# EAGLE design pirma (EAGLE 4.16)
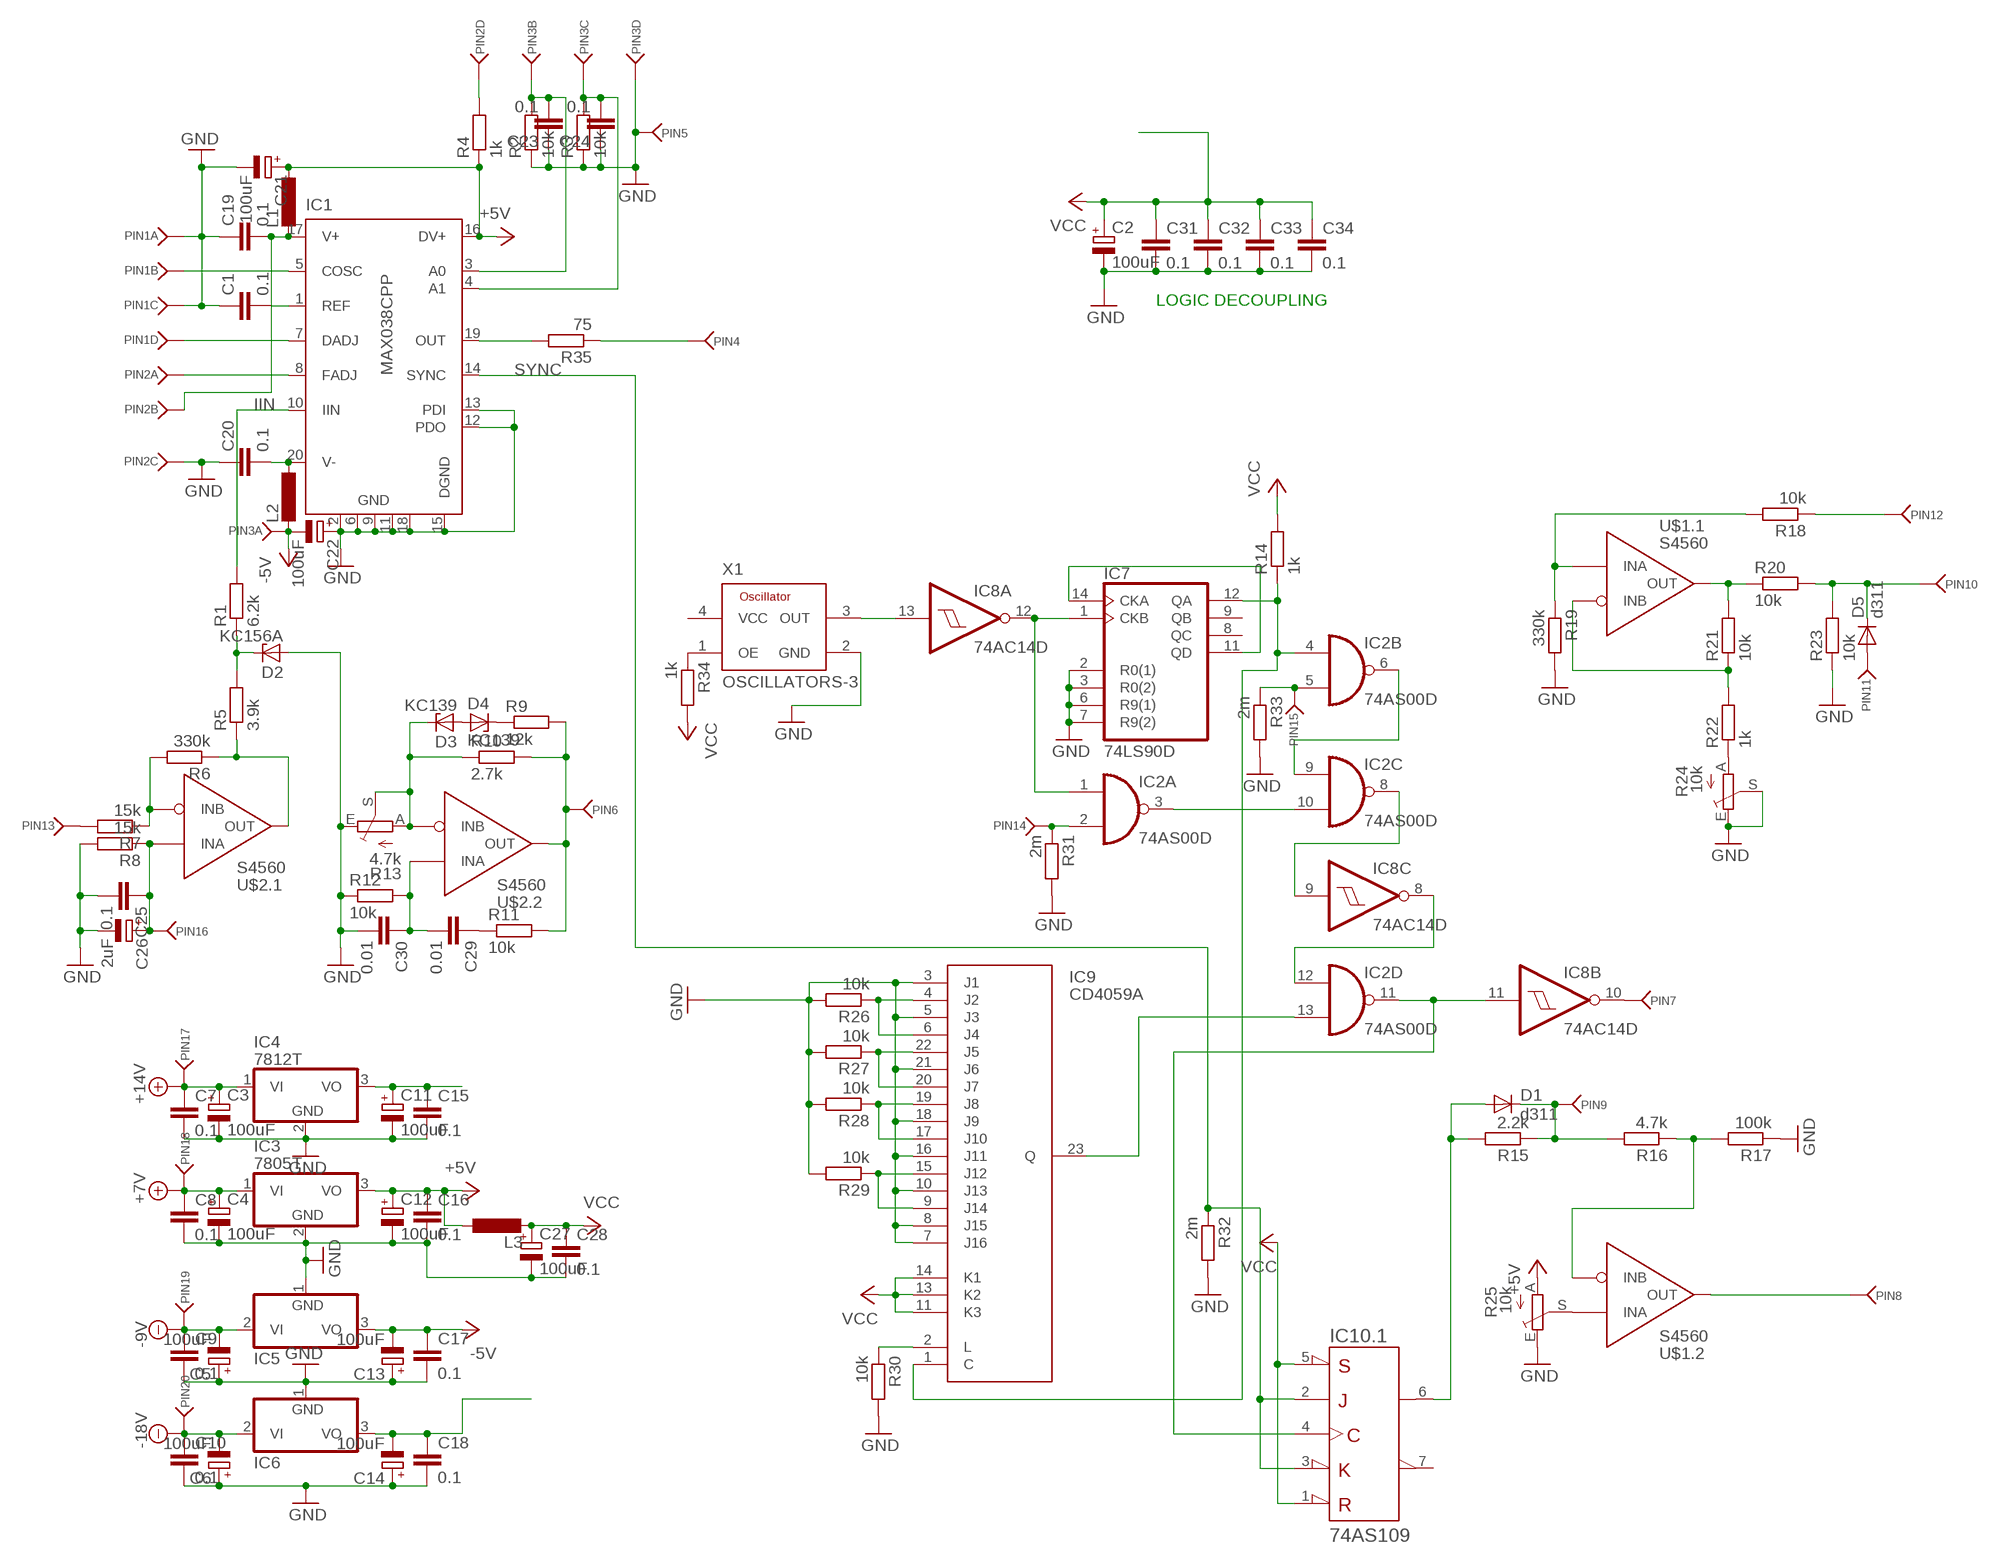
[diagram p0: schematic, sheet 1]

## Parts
C1  0.1  C-EUC1206K  [C1206K]
C2  100uF  CPOL-EUSMCD  [SMC_D]
C3  100uF  CPOL-EUSMCB  [SMC_B]
C4  100uF  CPOL-EUSMCB  [SMC_B]
C5  100uF  CPOL-EUSMCB  [SMC_B]
C6  100uF  CPOL-EUSMCD  [SMC_D]
C7  0.1  C-EUC1206K  [C1206K]
C8  0.1  C-EUC1206K  [C1206K]
C9  0.1  C-EUC1206K  [C1206K]
C10  0.1  C-EUC1206K  [C1206K]
C11  100uF  CPOL-EUSMCB  [SMC_B]
C12  100uF  CPOL-EUSMCD  [SMC_D]
C13  100uF  CPOL-EUSMCB  [SMC_B]
C14  100uF  CPOL-EUSMCB  [SMC_B]
C15  0.1  C-EUC1206K  [C1206K]
C16  0.1  C-EUC1206K  [C1206K]
C17  0.1  C-EUC1206K  [C1206K]
C18  0.1  C-EUC1206K  [C1206K]
C19  0.1  C-EUC1206K  [C1206K]
C20  0.1  C-EUC1206K  [C1206K]
C21  100uF  CPOL-EUSMCD  [SMC_D]
C22  100uF  CPOL-EUSMCB  [SMC_B]
C23  0.1  C-EUC1206K  [C1206K]
C24  0.1  C-EUC1206K  [C1206K]
C25  0.1  C-EUC1206K  [C1206K]
C26  2uF  CPOL-EUSMCB  [SMC_B]
C27  100uF  CPOL-EUSMCB  [SMC_B]
C28  0.1  C-EUC1206K  [C1206K]
C29  0.01  C-EUC1206K  [C1206K]
C30  0.01  C-EUC1206K  [C1206K]
C31  0.1  C-EUC1206K  [C1206K]
C32  0.1  C-EUC1206K  [C1206K]
C33  0.1  C-EUC1206K  [C1206K]
C34  0.1  C-EUC1206K  [C1206K]
D1  d311  DIODE-DO214AA  [DO214AA]
D2  KC156A  ZENER-DIODESMB  [SMB]
D3  KC139  ZENER-DIODESMB  [SMB]
D4  KC139  ZENER-DIODESMB  [SMB]
D5  d311  DIODE-DO214AA  [DO214AA]
IC1  MAX038CPP  [DIL20]
IC2  74AS00D  [SO14]
IC3  7805T  [TO220H]
IC4  7812T  [TO220H]
IC5  79L05Z  [TO92]
IC6  79L15Z  [TO92]
IC7  74LS90D  [SO14]
IC8  74AC14D  [SO14]
IC9  CD4059A  [DIL24-6]
IC10  74AS109  [DIL16]
L1  L-EUL4532C  [L4532M]
L2  L-EUL4532C  [L4532M]
L3  L-EUL4532C  [L4532M]
PIN1  PIN4  [PIN-T2-4]
PIN2  PIN4  [PIN-T2-4]
PIN3  PIN4  [PIN-T2-4]
PIN4  PINSMD  [PIN-T]
PIN5  PINSMD  [PIN-T]
PIN6  PINSMD2  [PIN-T2]
PIN7  PINSMD  [PIN-T]
PIN8  PINSMD  [PIN-T]
PIN9  PINSMD  [PIN-T]
PIN10  PINSMD  [PIN-T]
PIN11  PINSMD  [PIN-T]
PIN12  PINSMD  [PIN-T]
PIN13  PINSMD  [PIN-T]
PIN14  PINSMD  [PIN-T]
PIN15  PINSMD  [PIN-T]
PIN16  PINSMD  [PIN-T]
PIN17  PINSMD  [PIN-T]
PIN18  PINSMD  [PIN-T]
PIN19  PINSMD  [PIN-T]
PIN20  PINSMD  [PIN-T]
R1  6.2k  R-EU_M1206  [M1206]
R2  10k  R-EU_M1206  [M1206]
R3  10k  R-EU_M1206  [M1206]
R4  1k  R-EU_M1206  [M1206]
R5  3.9k  R-EU_M1206  [M1206]
R6  330k  R-EU_M1206  [M1206]
R7  15k  R-EU_M1206  [M1206]
R8  15k  R-EU_M1206  [M1206]
R9  12k  R-EU_M1206  [M1206]
R10  2.7k  R-EU_M1206  [M1206]
R11  10k  R-EU_M1206  [M1206]
R12  10k  R-EU_M1206  [M1206]
R13  4.7k  TRIM_EU-B25U  [B25U]
R14  1k  R-EU_M1206  [M1206]
R15  2.2k  R-EU_M1206  [M1206]
R16  4.7k  R-EU_M1206  [M1206]
R17  100k  R-EU_M1206  [M1206]
R18  10k  R-EU_M1206  [M1206]
R19  330k  R-EU_M1206  [M1206]
R20  10k  R-EU_M1206  [M1206]
R21  10k  R-EU_M1206  [M1206]
R22  1k  R-EU_M1206  [M1206]
R23  10k  R-EU_M1206  [M1206]
R24  10k  TRIM_EU-B25U  [B25U]
R25  10k  TRIM_EU-B25U  [B25U]
R26  10k  R-EU_M1206  [M1206]
R27  10k  R-EU_M1206  [M1206]
R28  10k  R-EU_M1206  [M1206]
R29  10k  R-EU_M1206  [M1206]
R30  10k  R-EU_M1206  [M1206]
R31  2m  R-EU_M1206  [M1206]
R32  2m  R-EU_M1206  [M1206]
R33  2m  R-EU_M1206  [M1206]
R34  1k  R-EU_M1206  [M1206]
R35  75  R-EU_M1206  [M1206]
U$1  S4560  [SO08]
U$2  S4560  [SO08]
X1  OSCILLATORS-3  [ASVK]

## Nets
+5V: C12.+ C16.1 C21.+ IC1.16(DV+) IC3.3(VO) L1.1 L3.1 R4.1 R25.A
+7V: C4.+ C8.1 IC3.1(VI) PIN18.P$1(P)
+14V: C3.+ C7.1 IC4.1(VI) PIN17.P$1(P)
-5V: C13.- C17.1 C22.- IC5.3(VO) L2.2 PIN3.P$1
-9V: C5.- C9.1 IC5.2(VI) PIN19.P$1(P)
-18V: C6.- C10.1 IC6.2(VI) PIN20.P$1(P)
GND: C1.1 C2.- C3.- C4.- C5.+ C6.+ C7.2 C8.2 C9.2 C10.2 C11.- C12.- C13.+ C14.+ C15.2 C16.2 C17.2 C18.2 C19.1 C20.1 C21.- C22.+ C23.1 C24.1 C25.2 C26.- C27.- C28.2 C30.2 C31.2 C32.2 C33.2 C34.2 D2.A IC1.2(GND) IC1.6(GND) IC1.9(GND) IC1.11(GND) IC1.12(PDO) IC1.13(PDI) IC1.15(DGND) IC1.18(GND) IC3.2(GND) IC4.2(GND) IC5.1(GND) IC6.1(GND) IC7.2(R0(1)) IC7.3(R0(2)) IC7.6(R9(1)) IC7.7(R9(2)) IC9.3(J1) IC9.5(J3) IC9.7(J16) IC9.8(J15) IC9.10(J13) IC9.16(J11) IC9.18(J9) IC9.21(J6) PIN1.P$1 PIN1.P$3 PIN2.P$3 PIN3.P$4 PIN5.P$1(P) R2.1 R3.1 R8.2 R12.1 R13.E R17.1 R19.2 R23.1 R24.E R24.S R25.E R26.2 R27.2 R28.2 R29.2 R30.2 R31.2 R32.2 R33.2 X1.2(GND)
IIN: IC1.10(IIN) R1.2
N$1: IC1.5(COSC) PIN1.P$2
N$2: IC1.7(DADJ) PIN1.P$4
N$3: IC1.8(FADJ) PIN2.P$1
N$4: C19.2 IC1.17(V+) L1.2 PIN2.P$2
N$5: C20.2 IC1.20(V-) L2.1
N$6: D2.C R1.1 R5.2
N$7: C1.2 IC1.1(REF)
N$8: C24.2 IC1.4(A1) PIN3.P$3 R3.2
N$9: C23.2 IC1.3(A0) PIN3.P$2 R2.2
N$10: PIN2.P$4 R4.2
N$11: R5.1 R6.1 U$2.1(.1:OUT)
N$12: R6.2 R7.1 U$2.2(.1:INB)
N$13: C25.1 C26.+ PIN16.P$1(P) R8.1 U$2.3(.1:INA)
N$14: D3.A D4.A
N$15: D4.C R9.1
N$16: D3.C R10.1 R13.A R13.S U$2.6(.2:INB)
N$17: PIN6.P$1(P) R9.2 R10.2 R11.2 U$2.7(.2:OUT)
N$18: C29.1 R11.1
N$19: C29.2 C30.1 R12.2 U$2.5(.2:INA)
N$20: IC8.13(A:I) X1.3(OUT)
N$21: R34.1 X1.1(OE)
N$22: IC2.1(A:I0) IC7.1(CKB) IC8.12(A:O)
N$23: R22.1 R24.A
N$24: IC7.11(QD) IC7.14(CKA)
N$25: IC2.4(B:I0) IC7.12(QA) IC9.1(C) R14.1
N$26: IC2.3(A:O) IC2.10(C:I1)
N$27: IC2.6(B:O) IC2.9(C:I0)
N$28: IC2.8(C:O) IC8.9(C:I)
N$29: IC2.12(D:I0) IC8.8(C:O)
N$30: IC2.11(D:O) IC8.11(B:I) IC10.4(.1:CLK)
N$31: R21.1 R22.2 U$1.2(.1:INB)
N$32: D1.A IC10.6(.1:Q) R15.2
N$33: D1.C PIN9.P$1(P) R15.1 R16.2
N$34: R16.1 R17.2 U$1.6(.2:INB)
N$35: R20.1 R21.2 U$1.1(.1:OUT)
N$36: R18.2 R19.1 U$1.3(.1:INA)
N$37: PIN12.P$1(P) R18.1
N$38: IC2.13(D:I1) IC9.23(Q)
N$39: R25.S U$1.5(.2:INA)
N$40: IC8.10(B:O) PIN7.P$1(P)
N$41: PIN8.P$1(P) U$1.7(.2:OUT)
N$42: D5.C PIN10.P$1(P) R20.2 R23.2
N$43: D5.A PIN11.P$1(P)
N$44: PIN13.P$1(P) R7.2
N$45: IC1.19(OUT) R35.2
N$46: PIN4.P$1(P) R35.1
N$47: IC9.4(J2) IC9.6(J4) R26.1
N$48: IC9.20(J7) IC9.22(J5) R27.1
N$49: IC9.17(J10) IC9.19(J8) R28.1
N$50: IC9.9(J14) IC9.15(J12) R29.1
N$51: IC9.2(L) R30.1
N$53: IC2.2(A:I1) PIN14.P$1(P) R31.1
N$55: IC2.5(B:I1) PIN15.P$1(P) R33.1
SYNC: IC1.14(SYNC) IC10.2(.1:J) IC10.3(.1:K\) R32.1
VCC: C2.+ C27.+ C28.1 C31.1 C32.1 C33.1 C34.1 IC9.11(K3) IC9.13(K2) IC9.14(K1) IC10.1(.1:CLR\) IC10.5(.1:PRE\) L3.2 R14.2 R34.2
VDD: C11.+ C15.1 IC4.3(VO)
VEE: C14.- C18.1 IC6.3(VO)
Unconnected: IC7.8(QC) IC7.9(QB) IC8.1(D:I) IC8.2(D:O) IC8.3(E:I) IC8.4(E:O) IC8.5(F:I) IC8.6(F:O) IC10.7(.1:Q\) IC10.9(.2:Q\) IC10.10(.2:Q) IC10.11(.2:PRE\) IC10.12(.2:CLK) IC10.13(.2:K\) IC10.14(.2:J) IC10.15(.2:CLR\)

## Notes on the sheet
- LOGIC DECOUPLING

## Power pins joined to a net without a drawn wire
GND: IC2.7(P:GND) IC7.10(GND) IC8.7(P:GND) IC9.12(GND) IC10.8(GND)
VCC: IC2.14(P:VCC) IC7.5(VCC) IC8.14(P:VCC) IC9.24(VCC) IC10.16(VCC) X1.4(VCC)
VDD: U$1.8(P:VDD) U$2.8(P:VDD)
VEE: U$1.4(P:VEE) U$2.4(P:VEE)

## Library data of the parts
C1 C7-C10 C15-C20 C23-C25 C28-C34 = rcl:C-EU: CAPACITOR, European symbol
C2-C6 C11-C14 C21 C22 C26 C27 = rcl:CPOL-EU: POLARIZED CAPACITOR, European symbol
D1 D5 = diode:DIODE-: DIODE
D2-D4 = diode:ZENER-DIODE: Z-Diode
IC1 = maxim:MAX038*: HIGH FREQUENCY WAVEFORM GENERATOR
IC2 = 74xx-eu:74*00: Quad 2-input NAND gate
IC3 IC4 = linear:78*: Positive VOLTAGE REGULATOR Source: http://cache.national.com/ds/LM/LM78L05.pdf http://www.fairchildsemi.com/ds/LM/LM7805.pdf
IC5 IC6 = linear:79*: Negative VOLTAGE REGULATOR
IC7 = 74xx-eu:74*90: Decade, divide by twelve and binary COUNTER
IC8 = 74xx-eu:74*14: Hex schmitt trigger INVERTER
IC9 = LevoROMS:CD4059A
IC10 = LevoROMS:74AS109
L1-L3 = rcl:L-EU: INDUCTOR, European symbol
PIN1-PIN3 = LevoROMS:PIN4: PIN4 SMD
PIN4-PIN20 = LevoROMS:PIN*: PIN
R1-R12 R14-R23 R26-R35 = rcl:R-EU_: RESISTOR, European symbol
R13 R24 R25 = pot:TRIM_EU-: POTENTIOMETER
U$1 U$2 = LevoROMS:S4560
X1 = m-pad-2.1:OSCILLATORS: Various Osccilators from various manufactures in various packages

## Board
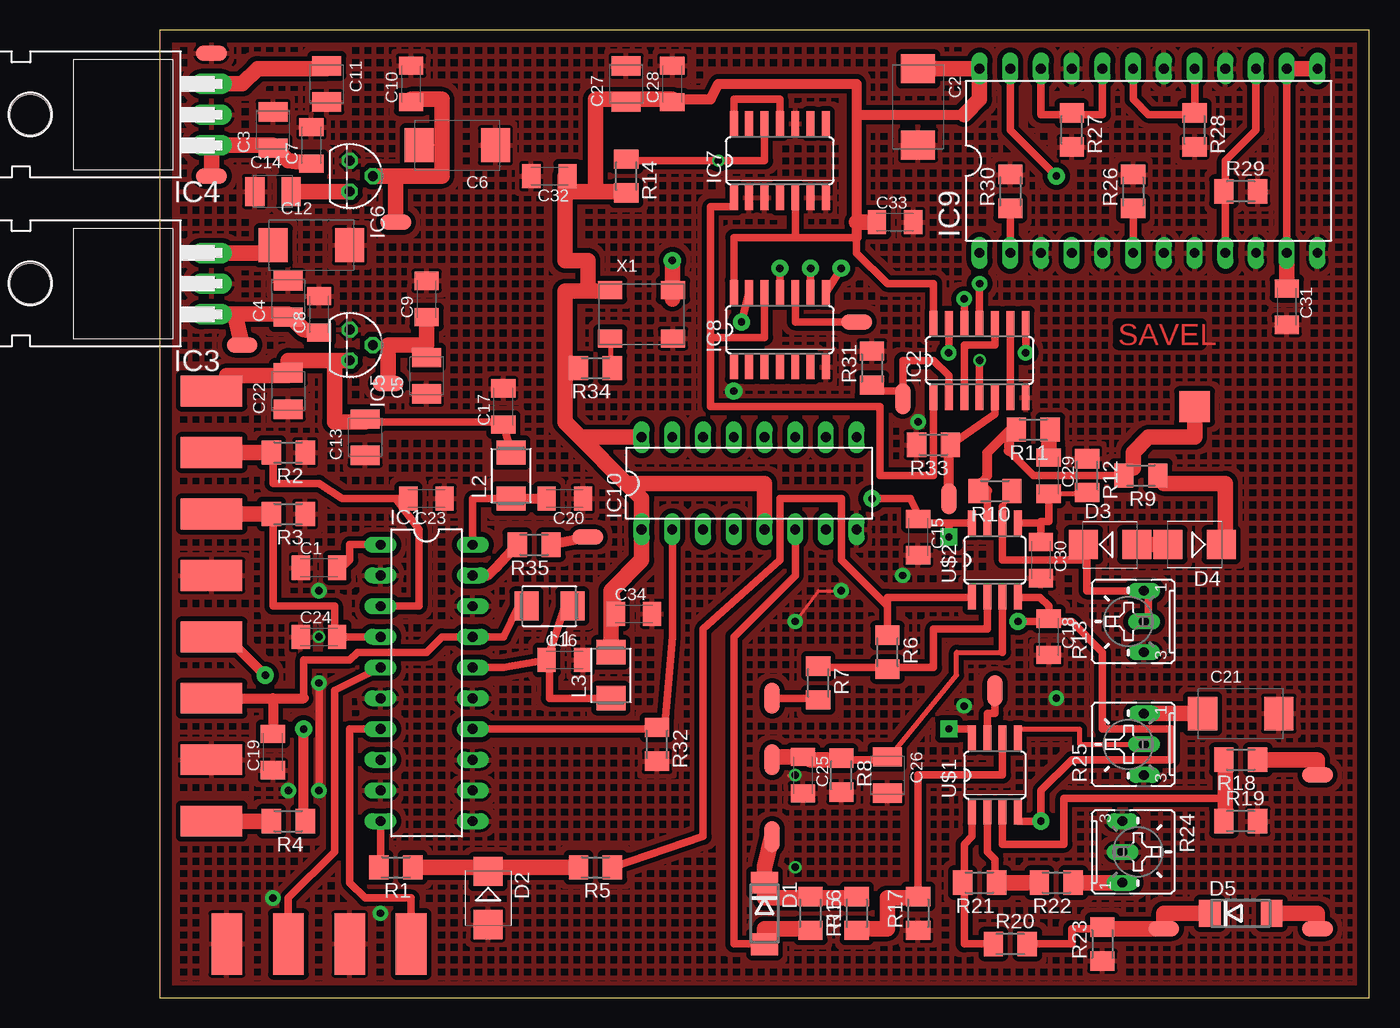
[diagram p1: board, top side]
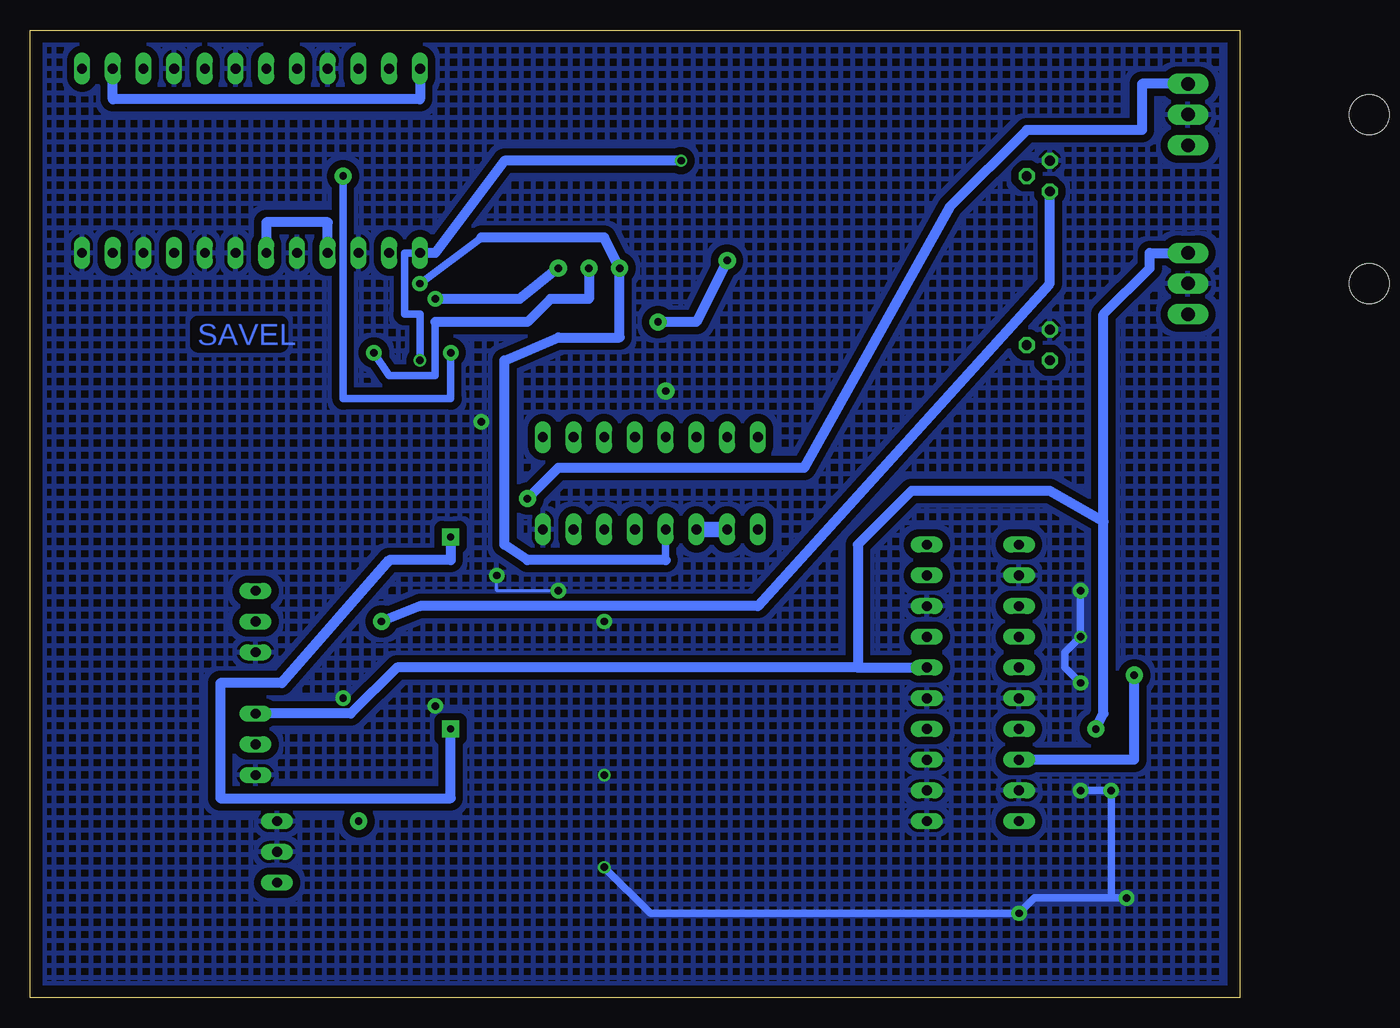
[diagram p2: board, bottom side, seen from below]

Size 100 x 80 mm. Coordinates in mm from the lower left corner, seen from the top.
Outline: 0,0 100,0 100,80 0,80 0,0
Copper layers (1*16): Top 0.035mm / dielectric 1.5mm / Bottom 0.035mm
Design rules "default": minimum track width 10mil, minimum drill 24mil, track to track 8mil, track to pad 8mil, pad to pad 8mil, via to via 8mil, smd to smd 6mil, copper to edge 40mil, drill to drill 8mil, minimum pad ring 10mil, minimum via ring 8mil, stop-mask expansion 4mil, vias tented up to drill 0mil, thermal gap 10mil

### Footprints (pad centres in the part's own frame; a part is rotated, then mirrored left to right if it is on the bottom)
C1206K = smd 1.5 x 2: 1 -1.5,0; 2 1.5,0
SMC_D = smd 2.4 x 2.8: + -3.15,0; - 3.15,0
SMC_B = smd 1.6 x 2.4: + -1.5,0; - 1.5,0
DO214AA = smd 1.8 x 2.2: A 2.55,0; C -2.55,0
SMB = smd 2.4 x 2.4: A 2.2,0; C -2.2,0
DIL20 = drill 0.813 long: 1 -11.43,-3.81; 2 -8.89,-3.81; 3 -6.35,-3.81; 4 -3.81,-3.81; 5 -1.27,-3.81; 6 1.27,-3.81; 7 3.81,-3.81; 8 6.35,-3.81; 9 8.89,-3.81; 10 11.43,-3.81; 11 11.43,3.81; 12 8.89,3.81; 13 6.35,3.81; 14 3.81,3.81; 15 1.27,3.81; 16 -1.27,3.81; 17 -3.81,3.81; 18 -6.35,3.81; 19 -8.89,3.81; 20 -11.43,3.81
SO14 = smd 0.66 x 2.032: 1 -3.81,-3.073; 2 -2.54,-3.073; 3 -1.27,-3.073; 4 0,-3.073; 5 1.27,-3.073; 6 2.54,-3.073; 7 3.81,-3.073; 8 3.81,3.073; 9 2.54,3.073; 10 1.27,3.073; 11 0,3.073; 12 -1.27,3.073; 13 -2.54,3.073; 14 -3.81,3.073
TO220H = drill 1.118 long: 1 -2.54,-10.16; 2 0,-10.16; 3 2.54,-10.16 | hole 3.302: 0,4.826
TO92 = drill 0.813 octagon: 1 -1.27,0; 2 0,1.905; 3 1.27,0
DIL24-6 = drill 0.813 long: 1 -13.97,-7.62; 2 -11.43,-7.62; 3 -8.89,-7.62; 4 -6.35,-7.62; 5 -3.81,-7.62; 6 -1.27,-7.62; 7 1.27,-7.62; 8 3.81,-7.62; 9 6.35,-7.62; 10 8.89,-7.62; 11 11.43,-7.62; 12 13.97,-7.62; 13 13.97,7.62; 14 11.43,7.62; 15 8.89,7.62; 16 6.35,7.62; 17 3.81,7.62; 18 1.27,7.62; 19 -1.27,7.62; 20 -3.81,7.62; 21 -6.35,7.62; 22 -8.89,7.62; 23 -11.43,7.62; 24 -13.97,7.62
DIL16 = drill 0.813 long: 1 -8.89,-3.81; 2 -6.35,-3.81; 3 -3.81,-3.81; 4 -1.27,-3.81; 5 1.27,-3.81; 6 3.81,-3.81; 7 6.35,-3.81; 8 8.89,-3.81; 9 8.89,3.81; 10 6.35,3.81; 11 3.81,3.81; 12 1.27,3.81; 13 -1.27,3.81; 14 -3.81,3.81; 15 -6.35,3.81; 16 -8.89,3.81
L4532M = smd 2 x 2.4: 1 -1.9,0; 2 1.9,0
PIN-T2-4 = smd 5.08 x 2.54: P$1 0,7.62; P$2 0,2.54; P$3 0,-2.54; P$4 0,-7.62
PIN-T = smd 2.54 x 1.27: P$1 0,0
PIN-T2 = smd 2.54 x 2.54: P$1 0,0
M1206 = smd 1.6 x 2: 1 -1.4,0; 2 1.4,0
B25U = drill 0.813 long: A 2.54,-0.889; E -2.54,-0.889; S 0,-0.889
SO08 = smd 0.66 x 2.032: 1 -1.905,-3.073; 2 -0.635,-3.073; 3 0.635,-3.073; 4 1.905,-3.073; 5 1.905,3.073; 6 0.635,3.073; 7 -0.635,3.073; 8 -1.905,3.073
ASVK = smd 2 x 1.5: 1 -2.6,-2; 2 2.6,-2; 3 2.6,2; 4 -2.6,2

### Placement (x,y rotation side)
C1  13.17,35.55 0 top
C2  62.7,73.66 270 top
C3  9.36,71.75 90 top
C4  10.63,57.78 90 top
C5  22.06,51.43 90 top
C6  24.6,70.48 180 top
C7  12.54,70.48 90 top
C8  13.17,56.51 90 top
C9  22.06,57.78 90 top
C10  20.79,75.56 90 top
C11  13.81,75.56 270 top
C12  12.54,62.23 0 top
C13  16.98,46.35 90 top
C14  9.36,66.67 0 top
C15  62.7,38.1 270 top
C16  33.49,27.93 0 top
C17  28.41,48.89 90 top
C18  73.5,29.84 270 top
C19  9.36,20.31 90 top
C20  33.49,41.27 180 top
C21  89.37,23.49 0 top
C22  10.63,50.16 90 top
C23  22.06,41.27 180 top
C24  13.17,29.84 0 top
C25  53.17,18.41 270 top
C26  60.16,18.41 270 top
C27  38.57,75.56 90 top
C28  42.38,75.56 90 top
C29  73.5,43.18 270 top
C30  72.86,36.19 270 top
C31  93.18,57.15 270 top
C32  32.22,67.94 180 top
C33  60.8,64.13 0 top
C34  39.2,31.74 0 top
D1  50,6.98 270 top
D2  27.14,8.25 270 top
D3  78.58,37.46 0 top
D4  85.56,37.46 180 top
D5  89.37,6.98 0 top
IC1  22.06,26.03 270 top
IC2  67.78,52.7 0 top
IC3  -5.88,59.05 90 top
IC4  -5.88,73.02 90 top
IC5  15.71,53.97 270 top
IC6  15.71,67.94 270 top
IC7  51.27,69.21 0 top
IC8  51.27,55.24 0 top
IC9  81.75,69.21 0 top
IC10  48.73,42.54 0 top
L1  32.22,32.38 180 top
L2  29.04,43.18 90 top
L3  37.3,26.66 90 top
PIN1  13.17,4.44 90 top
PIN2  4.28,22.22 0 top
PIN3  4.28,42.54 0 top
PIN4  35.39,38.1 180 top
PIN5  4.28,78.1 0 top
PIN6  85.56,48.89 0 top
PIN7  57.62,55.88 180 top
PIN8  69.05,25.39 90 top
PIN9  50.63,13.33 90 top
PIN10  83.02,5.71 0 top
PIN11  95.72,5.71 0 top
PIN12  95.72,18.41 0 top
PIN13  50.63,24.76 270 top
PIN14  61.43,49.53 270 top
PIN15  65.24,41.27 270 top
PIN16  50.63,19.68 90 top
PIN17  4.28,67.94 0 top
PIN18  6.82,53.97 0 top
PIN19  18.88,50.8 0 top
PIN20  19.52,64.13 0 top
R1  19.52,10.79 180 top
R2  10.63,45.08 180 top
R3  10.63,40 180 top
R4  10.63,14.6 180 top
R5  36.03,10.79 180 top
R6  60.16,28.57 270 top
R7  54.45,26.03 270 top
R8  56.35,18.41 270 top
R9  81.11,43.18 180 top
R10  69.05,41.91 180 top
R11  72.22,46.98 180 top
R12  76.67,43.18 270 top
R13  80.48,31.11 90 top
R14  38.57,67.94 270 top
R15  53.81,6.98 270 top
R16  57.62,6.98 90 top
R17  62.7,6.98 90 top
R18  89.37,19.68 180 top
R19  89.37,14.6 0 top
R20  70.32,4.44 0 top
R21  67.78,9.52 180 top
R22  74.13,9.52 180 top
R23  77.94,4.44 90 top
R24  80.48,12.06 270 top
R25  80.48,20.95 90 top
R26  80.48,66.67 90 top
R27  75.4,71.75 270 top
R28  85.56,71.75 270 top
R29  89.37,66.67 0 top
R30  70.32,66.67 90 top
R31  58.89,52.07 90 top
R32  41.11,20.95 270 top
R33  63.97,45.72 180 top
R34  36.03,52.07 180 top
R35  30.95,37.46 180 top
U$1  69.05,18.41 0 top
U$2  69.05,36.19 0 top
X1  39.84,56.51 0 top

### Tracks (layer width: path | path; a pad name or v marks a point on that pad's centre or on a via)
+5V  (via drill 0.61 pad 1.42)
  Top 0.254: C21.+ 86.83,23.49 | R4.1 11.9,14.6 | C16.1 32.22,28.57 | 9.36,61.59 C12.+
  Top 0.61: L3.1 32.22,24.76 32.22,28.57 33.49,32.38 L1.1 | C16.1 28.41,27.3 IC1.16
  Top 0.813: 11.9,14.6 v11.9,22.22
  Top 1.27: R25.A C21.+ | IC3.3 9.36,61.59
  Bottom 0.254: R25.A 81.75,23.49
  Bottom 0.813: v11.9,22.22 11.27,23.49 11.27,39.37 | R25.A 73.5,23.49 69.69,27.3 31.58,27.3 | 31.58,27.3 IC1.16 | 11.27,39.37 11.27,56.51 7.46,60.32 7.46,61.59 IC3.3 | 11.27,39.37 15.71,41.91 27.14,41.91 31.58,37.46 31.58,27.3
+7V
  Top 0.254: 10.63,56.51 C4.+
  Top 1.27: C8.1 11.9,55.24 10.63,56.51 6.18,56.51 | 6.18,56.51 IC3.1 | PIN18.P$1 6.18,56.51
+14V
  Top 0.254: 9.36,70.48 C3.+
  Top 1.27: C7.1 10.63,69.21 9.36,70.48 IC4.1 PIN17.P$1
-5V
  Top 0.254: L2.2 | 28.41,47.62 C17.1 | 5.55,51.43 5.55,50.16 PIN3.P$1 | 10.63,51.43 C22.- | 16.98,47.62 C13.-
  Top 0.61: C17.1 L2.2 | 16.98,47.62 28.41,47.62
  Top 1.27: 5.55,51.43 10.63,51.43 | 14.44,52.7 10.63,52.7 C22.- | 14.44,52.7 IC5.3 | 16.98,47.62 14.44,47.62 14.44,52.7
-9V
  Top 0.254: 22.06,53.97 C5.- 22.06,52.7 | C9.1 22.06,56.51
  Top 0.61: 18.88,53.97 IC5.2
  Top 1.27: C9.1 22.06,53.97 18.88,53.97 PIN19.P$1
-18V
  Top 0.254: 20.79,74.29 C10.1 | 23.33,70.48 C6.-
  Top 1.27: 20.79,74.29 23.33,74.29 23.33,70.48 23.33,67.94 19.52,67.94 | 19.52,67.94 IC6.2 | PIN20.P$1 19.52,67.94
GND  (via drill 0.61, 0.61 pad 1.27, 0.61 pad 1.42)
  Top 0.254: v13.17,29.84 13.11,29.84 | v13.17,33.65 13.11,33.65 | v52.54,31.11 54.45,33.65 v56.35,33.65 | 51.98,18.35 v52.54,18.41
  Top 0.61: v13.17,17.14 v13.17,26.03
  Bottom 0.254: v56.35,33.65 61.43,33.65 v61.43,34.92
  Bottom 0.61: v52.54,10.79 48.73,6.98 v18.25,6.98 16.98,8.25 10.63,8.25 | v9.36,8.25 10.63,8.25 | 10.63,8.25 v10.63,17.14 v13.17,17.14 | v13.17,26.03 14.44,27.3 14.44,28.57 v13.17,29.84 v13.17,33.65
  other vias: 47.46,50.16 62.7,47.62 66.51,24.12 74.13,24.76
  pour Top (isolate 0.406, hatched): -0.17,79.37 -0.17,0.63 99.53,0.63 99.53,79.37
  pour Bottom (isolate 0.61, hatched): 99.53,79.37 0.47,79.37 0.47,0.63 99.53,0.63
IIN
  Top 0.254: R1.2 18.25,10.79
  Top 0.61: 18.25,10.79 IC1.10
N$1
  Top 0.61: IC1.5 14.44,25.39 14.44,12.06 10.63,8.25 PIN1.P$2
N$2
  Top 0.61: IC1.7 15.71,22.22 15.71,9.52 16.98,8.25 20.79,8.25 PIN1.P$4
N$3  (via drill 0.61 pad 1.42)
  Top 0.254: 5.55,29.84 PIN2.P$1
  Top 0.813: v8.73,26.66 5.55,29.84
  Bottom 0.813: v8.73,26.66 8.73,19.68 IC1.8
N$4
  Top 0.61: L1.2 29.68,32.38 28.41,29.84 IC1.17 23.33,29.84 22.06,28.57 16.34,28.57 15.71,27.93 11.9,27.93 11.9,24.76
  Top 0.813: PIN2.P$2 9.36,24.76 | 9.36,24.76 11.9,24.76 | 9.36,24.76 C19.2
N$5
  Top 0.254: 28.41,41.27 L2.1
  Top 0.61: 28.41,41.27 25.87,41.27 IC1.20 | L2.1 29.68,41.27
  Top 0.813: 29.68,41.27 C20.2
N$6
  Top 0.254: R1.1 20.79,10.79 | R5.2 34.76,10.79 | 27.14,10.79 D2.C
  Top 1.27: R1.1 27.14,10.79 R5.2
N$7
  Top 0.254: C1.2 14.44,34.92
  Top 0.61: 14.44,34.92 15.71,36.19 15.71,37.46 IC1.1
N$8
  Top 0.254: 14.44,29.84 C24.2 | 9.36,40 R3.2
  Top 0.61: C24.2 IC1.4 | 14.44,29.84 14.44,32.38 9.36,32.38 9.36,40
  Top 1.27: R3.2 PIN3.P$3
N$9
  Top 0.254: R2.2 9.36,45.08 | 19.52,41.27 18.25,41.27
  Top 0.61: 19.52,41.27 15.08,41.27 13.17,42.54 9.36,42.54 9.36,45.08 | 19.52,41.27 C23.2 | 19.52,41.27 21.42,38.73 21.42,32.38 IC1.3
  Top 1.27: PIN3.P$2 R2.2
N$10
  Top 0.254: R4.2 9.36,14.6
  Top 1.27: PIN2.P$4 R4.2
N$11
  Top 0.254: R5.1 37.3,10.79 | R6.1 60.16,29.84
  Top 0.61: R5.1 44.92,13.33 44.92,30.47 51.27,36.19 51.27,41.27 56.35,41.27 56.35,36.19 60.16,32.38 | 60.16,32.38 R6.1 | U$2.1 60.16,33.12 60.16,32.38
N$12
  Top 0.254: R7.1 55.08,27.3
  Top 0.406: 60.16,27.3 R6.2
  Top 0.61: 55.08,27.3 60.16,27.3 63.97,27.3 63.97,30.47 68.41,30.47 U$2.2
N$13
  Top 0.254: C25.1 53.81,19.68 | 56.35,19.68 R8.1
  Top 0.406: 69.69,28.57 65.88,28.57 65.88,26.66 60.16,19.68 C26.+ | PIN16.P$1 50.87,19.91
  Top 0.61: 56.35,19.68 60.16,19.68 | 69.69,28.57 U$2.3
  Top 1.27: 53.81,19.68 56.35,19.68 | 50.87,19.91 C25.1
N$14
  Top 1.27: D3.A D4.A
N$15
  Top 0.254: R9.1 83.02,42.54 | 88.1,37.46 D4.C
  Top 1.27: 83.02,42.54 88.1,42.54 88.1,37.46
N$16
  Top 0.406: 69.69,40.64 R10.1 | D3.C 76.67,37.46 76.67,36.19
  Top 0.61: R13.S 81.75,31.11 81.75,33.65 R13.A 76.67,33.65 76.67,36.19 69.69,36.19 U$2.6 69.69,40.64
N$17
  Top 0.254: R9.2 80.48,43.81
  Top 0.406: 70.19,46.86 R11.2 | 67.78,42.54 R10.2 | R9.2 79.84,43.18
  Top 0.61: U$2.7 68.41,41.91 | 67.78,42.54 68.41,43.18 | 70.19,45.21 72.22,43.18 R9.2
  Top 0.813: 68.41,41.91 67.78,42.54 | 68.41,43.18 68.41,45.08 70.19,46.86 70.19,45.21
  Top 1.27: 80.48,43.81 80.48,45.08 81.75,46.35 85.56,46.35 PIN6.P$1
N$18
  Top 0.254: 73.5,46.35 R11.1
  Top 1.27: C29.1 73.5,46.35
N$19
  Top 0.406: 72.86,39.37 72.76,39.26 | 72.86,41.91 C29.2 75.8,41.68 76.03,41.91 R12.2
  Top 0.61: C30.1 72.86,39.37 73.5,39.37 C29.2 | 72.76,39.26 U$2.5
N$20  (via drill 0.61 pad 1.42)
  Top 0.254: X1.3 42.38,57.78
  Top 0.61: v48.09,55.88 IC8.13
  Top 1.27: 42.38,57.78 v42.38,60.96
  Bottom 0.813: v42.38,60.96 44.92,55.88 v48.09,55.88
N$21
  Top 0.406: 37.3,54.51 37.3,54.61 | 37.3,54.51 X1.1 | R34.1 37.3,52.07 37.3,54.51
N$22
  Top 0.254: 47.46,65.4 IC7.1
  Top 0.61: 45.55,54.61 50,54.61 IC8.12 | 45.55,54.61 45.55,65.4 47.46,65.4 | 45.55,54.61 45.55,48.89 59.52,48.89 59.52,43.18 63.97,43.18 IC2.1
N$23
  Top 0.254: R22.1 75.4,9.52
  Top 1.27: R22.1 R24.A
N$24
  Top 0.61: IC7.14 47.46,74.29 51.27,74.29 IC7.11
N$25  (via drill 0.61)
  Top 0.254: R14.1 38.57,69.21
  Top 0.61: 38.57,69.21 v46.19,69.21 50,69.21 IC7.12 | v67.78,52.7 IC2.4
  Bottom 0.61: v67.78,52.7 67.78,56.51 69.05,56.51 69.05,61.59 IC9.1
  Bottom 0.813: v46.19,69.21 60.8,69.21 66.51,61.59 IC9.1
N$26
  Top 0.61: IC2.3 66.51,53.97 69.05,53.97 IC2.10
N$27
  Top 0.61: IC2.6 IC2.9
N$28  (via drill 0.61 pad 1.27, 0.61 pad 1.42)
  Top 0.61: IC8.9 v53.81,60.32 | v71.59,53.34 IC2.8
  Bottom 0.61: 66.51,55.88 66.51,51.43 70.32,51.43 v71.59,53.34
  Bottom 0.813: v53.81,60.32 53.81,57.78 56.98,57.78 58.89,55.88 66.51,55.88
N$29  (via drill 0.61 pad 1.27, 0.61 pad 1.42)
  Top 0.61: IC8.8 v56.35,60.32 | v66.51,57.78 IC2.12
  Bottom 0.813: v56.35,60.32 59.52,57.78 v66.51,57.78
N$30  (via drill 0.61 pad 1.27, 0.61 pad 1.42)
  Top 0.61: v67.78,59.05 IC2.11 | v51.27,60.32 IC8.11
  Bottom 0.61: 62.7,62.86 v67.78,59.05 | 47.46,36.19 IC10.4
  Bottom 0.813: 62.7,62.86 52.54,62.86 v51.27,60.32 51.27,54.61 56.35,54.61 60.8,52.7 60.8,37.46 58.89,36.19 47.46,36.19
N$31
  Top 0.254: R21.1 69.05,9.52 | R22.2 72.86,9.52
  Top 0.61: 69.05,9.52 69.05,11.43 68.41,12.06 U$1.2
  Top 1.27: R21.1 R22.2
N$32
  Top 0.254: 53.81,5.71 R15.2 | D1.A
  Top 0.61: D1.A 47.46,4.44 47.46,29.84 52.54,34.92 IC10.6
  Top 1.27: 53.81,5.71 50,5.71 D1.A
N$33
  Top 0.254: 57.62,8.25 R16.2 | 53.81,8.25 R15.1 | D1.C
  Top 1.27: 57.62,8.25 53.81,8.25 50,8.25 D1.C 50,10.79 PIN9.P$1
N$34
  Top 0.254: R16.1 57.62,5.71 | 62.7,8.25 R17.2
  Top 0.61: U$1.6 69.69,18.41 62.7,18.41 R17.2
  Top 1.27: 57.62,5.71 60.16,5.71 60.16,8.25 62.7,8.25
N$35
  Top 0.254: R20.1 69.05,4.44 | 66.51,9.52 R21.2
  Top 0.61: R20.1 66.51,4.44 66.51,9.52 66.51,12.7 67.14,13.33 U$1.1
N$36
  Top 0.254: 88.1,14.6 R19.1 | 88.1,19.68 R18.2
  Top 0.61: U$1.3 69.69,12.7 74.77,12.7 74.77,16.5 88.1,16.5
  Top 1.27: 88.1,14.6 88.1,16.5 88.1,19.68
N$37
  Top 0.254: R18.1 90.64,19.68
  Top 1.27: R18.1 95.72,19.68 PIN12.P$1
N$38  (via drill 0.61 pad 1.27, 0.61 pad 1.42)
  Top 0.61: v74.13,67.94 70.32,71.75 IC9.23 | v65.24,53.34 IC2.13
  Bottom 0.61: v65.24,53.34 65.24,49.53 74.13,49.53 v74.13,67.94
N$39
  Top 0.406: R25.S 76.03,20.95 76.03,22.22 70.95,22.22 U$1.5
N$40
  Top 0.61: IC8.10 52.54,55.88 PIN7.P$1
N$41
  Top 0.61: U$1.7 68.41,23.49 69.05,23.49 PIN8.P$1
N$42
  Top 0.254: D5.C | R20.2 71.59,4.44 | 77.94,5.71 R23.2
  Top 0.61: R20.2 75.4,4.44 75.4,5.71 77.94,5.71
  Top 1.27: D5.C 83.02,6.98 PIN10.P$1 77.94,5.71
N$43
  Top 0.254: D5.A
  Top 1.27: D5.A 95.72,6.98 PIN11.P$1
N$44
  Top 0.254: R7.2 55.08,24.76 54.45,24.76
  Top 0.61: PIN13.P$1 54.45,24.76
N$45
  Top 0.813: R35.2 27.77,35.55 27.14,34.92 IC1.19
N$46
  Top 0.254: R35.1 32.22,37.46
  Top 0.813: 32.22,37.46 PIN4.P$1
N$47
  Top 0.254: R26.1 80.48,65.4
  Top 0.61: IC9.6 R26.1
  Bottom 0.813: IC9.4 75.4,64.13 80.48,64.13 IC9.6
N$48
  Top 0.254: 77.94,75.56 IC9.20 | 75.4,73.02 R27.1
  Top 0.61: IC9.22 72.86,73.02 75.4,73.02 77.94,73.02 77.94,75.56
N$49
  Top 0.254: 85.56,73.02 R28.1
  Top 0.61: R28.1 IC9.17 | 85.56,73.02 81.75,73.02 80.48,74.29 IC9.19
N$50
  Top 0.254: 88.1,66.67 R29.1
  Top 0.61: IC9.9 88.1,66.67 88.1,69.21 90.64,71.75 IC9.15
N$51
  Top 0.254: R30.1 70.32,65.4
  Top 0.61: IC9.2 R30.1
N$53
  Top 0.254: 61.43,50.16 PIN14.P$1 | R31.1 58.89,50.16
  Top 0.61: 58.89,50.16 61.43,50.16 61.43,52.7 63.97,52.7 65.24,51.43 IC2.2
N$55
  Top 0.406: R33.1 65.24,45.08 65.24,45.72
  Top 0.61: R33.1 69.05,48.26 IC2.5
  Top 0.813: PIN15.P$1 65.24,45.08
SYNC
  Top 0.254: 39.84,22.22 R32.1
  Top 0.61: IC1.14 39.84,22.22 41.74,22.22 42.38,29.84 IC10.2
  Bottom 1.27: IC10.2 IC10.3
VCC
  Top 0.254: 33.49,67.94 C32.1 | 38.57,66.67 R14.2 | 38.57,74.29 C27.+ | 42.38,74.29 C28.1 | 33.49,52.7 34.76,52.7 R34.2
  Top 0.406: X1.4 37.3,58.51 37.3,58.41 36.03,58.41
  Top 0.61: IC9.14 IC9.11 | 52.54,62.86 57.62,62.86 57.62,61.59 60.16,59.05 63.97,59.05 IC2.14 | 52.54,62.86 IC7.5 | IC8.14 47.46,62.86 52.54,62.86
  Top 0.813: 42.38,74.29 45.55,74.29 46.19,75.56 57.62,75.56 57.62,73.02 | 57.62,73.02 57.62,64.13 57.62,62.86 | 57.62,73.02 66.51,73.02
  Top 1.27: L3.2 37.3,33.65 | 37.3,33.65 39.84,36.19 IC10.1 39.84,41.27 38.57,42.54 | 34.76,46.35 33.49,47.62 33.49,52.7 33.49,58.41 36.03,58.41 35.39,58.41 35.39,60.96 33.49,60.96 33.49,66.67 | 38.57,42.54 34.76,46.35 | IC9.14 IC9.13 | C2.+ IC9.24 67.78,74.29 66.51,73.02 | 42.38,74.29 38.57,74.29 36.03,74.29 36.03,66.67 | 33.49,66.67 33.49,67.94 | 36.03,66.67 38.57,66.67 | 33.49,66.67 36.03,66.67 | IC9.11 C31.1 | 57.62,64.13 C33.1 | 37.3,33.65 C34.1 | 34.76,46.35 IC10.16 | 38.57,42.54 50,42.54 IC10.5
  Bottom 0.813: IC9.14 93.18,74.29 67.78,74.29 IC9.24
VDD  (via drill 0.6 pad 1.42, 0.61 pad 1.42)
  Top 0.254: 13.81,76.83 C11.+ | 62.7,40 C15.1
  Top 0.406: C15.1 62.7,39.37 62.8,39.26 | 67.14,22.22 U$1.8
  Top 0.61: 62.7,40 62.06,41.27 v58.89,41.27 | 62.8,39.26 65.24,39.26 | 65.24,39.26 U$2.8 | v65.24,22.22 67.14,22.22 | 65.24,39.26 v65.24,38.1
  Top 1.27: 13.81,76.83 8.09,76.83 6.82,75.56 IC4.3
  Bottom 0.813: v58.89,41.27 56.35,43.81 36.03,43.81 23.96,65.4 17.61,71.75 8.09,71.75 8.09,75.56 IC4.3 | v65.24,22.22 65.24,16.5 84.29,16.5 84.29,26.03 79.21,26.03 70.32,36.19 65.24,36.19 v65.24,38.1
VEE  (via drill 0.6 pad 1.42, 0.61 pad 1.42)
  Top 0.254: C14.- 10.63,66.67 | 72.86,31.11 C18.1 74.13,31.11
  Top 0.406: C18.1 73.5,31.11 | 70.95,14.6 U$1.4
  Top 0.61: v70.95,31.11 72.86,31.11 | U$2.4 72.76,33.12 73.5,32.38 C18.1 | 70.95,14.6 v72.86,14.6 72.86,17.14 75.4,19.68 83.66,19.68 83.66,22.22 77.94,22.22 77.94,28.57 75.4,31.11 74.13,31.11
  Top 1.27: IC6.3 C14.-
  Bottom 0.813: v70.95,31.11 67.78,32.38 39.84,32.38 15.71,59.05 IC6.3

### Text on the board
Top: SAVEL
Bottom: SAVEL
